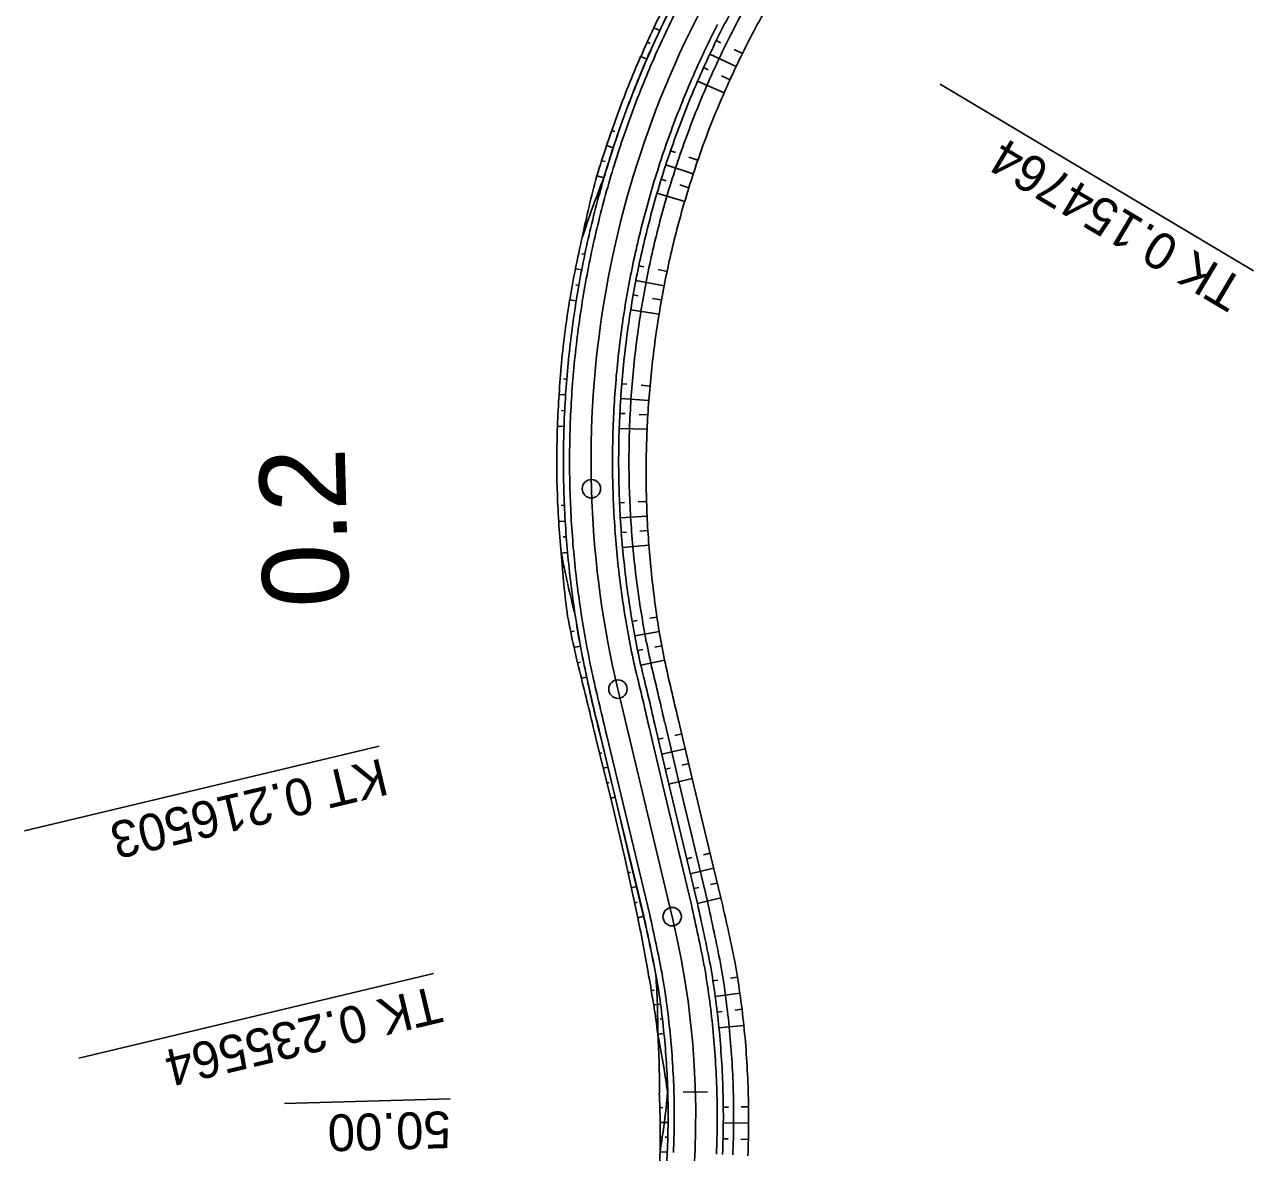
# Model space of a CAD drawing. Extents: x -481645 to -478728, y -1113199 to -1110710.
# Drawn here: x -479577.1 to -479477, y -1112599.2 to -1112507.3 of the extents above; entities that cross this region are included whole.
import ezdxf

# ---------------------------------------------------------------- set-up
doc = ezdxf.new("R2010")
doc.units = 0
for name, color, linetype in [('CP14_HRANA_TELESO', 7, 'Continuous'), ('CP14_OSA', 7, 'Continuous'), ('CP14_PRIKOP', 7, 'Continuous'), ('CP1_HATCH_SLOPE_L', 7, 'Continuous'), ('CP1_HATCH_SLOPE_R', 7, 'Continuous'), ('CP1_HLBODY', 7, 'Continuous'), ('CP1_HRANA_TELESO', 7, 'Continuous'), ('CP1_OSA', 7, 'Continuous'), ('CP1_STANICENI', 7, 'Continuous'), ('CP1_VOZOVKA', 7, 'Continuous'), ('CP1_ZPEVKRAJ', 7, 'Continuous')]:
    doc.layers.add(name, color=color, linetype=linetype)

msp = doc.modelspace()

# ---------------------------------------------------------------- linework, layer by layer
at = {"layer": 'CP14_HRANA_TELESO'}
for p, q in [((-479520.79, -1112508.65), (-479520.41, -1112508.84)), ((-479521.31, -1112509.75), (-479519.17, -1112510.76)), ((-479519.34, -1112509.36), (-479518.66, -1112509.7)), ((-479521.82, -1112510.85), (-479521.44, -1112511.02)), ((-479522.31, -1112511.96), (-479520.14, -1112512.9)), ((-479520.36, -1112511.51), (-479519.66, -1112511.83)), ((-479524.51, -1112517.62), (-479524.12, -1112517.76)), ((-479524.9, -1112518.77), (-479522.67, -1112519.5)), ((-479523.01, -1112518.14), (-479522.29, -1112518.39)), ((-479525.27, -1112519.93), (-479524.87, -1112520.06)), ((-479523.75, -1112520.4), (-479523.03, -1112520.63)), ((-479525.62, -1112521.09), (-479523.36, -1112521.75)), ((-479527.09, -1112526.99), (-479526.68, -1112527.07)), ((-479525.53, -1112527.31), (-479524.8, -1112527.47)), ((-479527.33, -1112528.18), (-479525.03, -1112528.62)), ((-479527.55, -1112529.37), (-479527.14, -1112529.45)), ((-479525.99, -1112529.65), (-479525.24, -1112529.78)), ((-479527.75, -1112530.57), (-479525.44, -1112530.94)), ((-479528.48, -1112536.6), (-479528.07, -1112536.63)), ((-479526.91, -1112536.73), (-479526.18, -1112536.79)), ((-479528.57, -1112537.81), (-479526.28, -1112537.96)), ((-479528.64, -1112539.02), (-479528.22, -1112539.04)), ((-479527.08, -1112539.1), (-479526.36, -1112539.14)), ((-479528.69, -1112540.24), (-479526.42, -1112540.31)), ((-479528.67, -1112546.31), (-479528.25, -1112546.29)), ((-479527.15, -1112546.24), (-479526.46, -1112546.21)), ((-479528.6, -1112547.52), (-479526.42, -1112547.39)), ((-479528.52, -1112548.73), (-479528.1, -1112548.7)), ((-479527.02, -1112548.62), (-479526.36, -1112548.57)), ((-479528.42, -1112549.95), (-479526.28, -1112549.75)), ((-479527.64, -1112555.97), (-479527.22, -1112555.9)), ((-479526.21, -1112555.72), (-479525.61, -1112555.62)), ((-479527.42, -1112557.16), (-479525.42, -1112556.79)), ((-479525.79, -1112558.07), (-479525.22, -1112557.96)), ((-479527.19, -1112558.35), (-479526.78, -1112558.27)), ((-479526.94, -1112559.54), (-479524.99, -1112559.12)), ((-479525.51, -1112565.58), (-479525.11, -1112565.49)), ((-479524.15, -1112565.26), (-479523.6, -1112565.13)), ((-479525.22, -1112566.8), (-479523.32, -1112566.35)), ((-479524.93, -1112568.02), (-479524.53, -1112567.92)), ((-479523.57, -1112567.69), (-479523.03, -1112567.56)), ((-479524.64, -1112569.23), (-479522.74, -1112568.78)), ((-479521.84, -1112574.99), (-479521.3, -1112574.86)), ((-479523.19, -1112575.31), (-479522.78, -1112575.21)), ((-479522.9, -1112576.53), (-479521, -1112576.07)), ((-479522.61, -1112577.74), (-479522.2, -1112577.65)), ((-479521.25, -1112577.42), (-479520.7, -1112577.29)), ((-479522.32, -1112578.96), (-479520.41, -1112578.5)), ((-479519.64, -1112585.05), (-479519.06, -1112584.96)), ((-479521.06, -1112585.27), (-479520.65, -1112585.2)), ((-479520.87, -1112586.54), (-479518.86, -1112586.27)), ((-479520.71, -1112587.82), (-479520.3, -1112587.77)), ((-479519.28, -1112587.65), (-479518.69, -1112587.58)), ((-479520.57, -1112589.1), (-479518.54, -1112588.9)), ((-479520.22, -1112595.54), (-479519.8, -1112595.54)), ((-479518.77, -1112595.53), (-479518.16, -1112595.52)), ((-479520.22, -1112596.83), (-479518.15, -1112596.85)), ((-479520.24, -1112598.12), (-479519.82, -1112598.13)), ((-479518.78, -1112598.16), (-479518.16, -1112598.18))]:
    msp.add_line(p, q, dxfattribs=at)
at = {"layer": 'CP14_OSA'}
msp.add_circle((-479530.96, -1112545.16), 0.75, dxfattribs=at)
at = {"layer": 'CP14_PRIKOP'}
for p, q in [((-479525.38, -1112507.83), (-479525.87, -1112507.6)), ((-479526.17, -1112508.88), (-479526.42, -1112508.77)), ((-479525.92, -1112509), (-479525.93, -1112508.99)), ((-479526.44, -1112510.17), (-479526.94, -1112509.95)), ((-479529.04, -1112516.06), (-479529.3, -1112515.98)), ((-479528.77, -1112516.16), (-479528.77, -1112516.16)), ((-479529.18, -1112517.38), (-479529.72, -1112517.2)), ((-479529.85, -1112518.51), (-479530.13, -1112518.43)), ((-479529.57, -1112518.6), (-479529.57, -1112518.6)), ((-479529.93, -1112519.83), (-479530.51, -1112519.66)), ((-479531.99, -1112525.96), (-479531.99, -1112525.96)), ((-479531.5, -1112526.06), (-479531.74, -1112526.01)), ((-479531.75, -1112527.32), (-479532.26, -1112527.23)), ((-479532.5, -1112528.5), (-479532.5, -1112528.5)), ((-479531.98, -1112528.59), (-479532.24, -1112528.54)), ((-479532.2, -1112529.85), (-479532.73, -1112529.77)), ((-479533.5, -1112536.19), (-479533.5, -1112536.19)), ((-479532.97, -1112536.23), (-479533.23, -1112536.21)), ((-479533.06, -1112537.51), (-479533.6, -1112537.48)), ((-479533.67, -1112538.77), (-479533.67, -1112538.77)), ((-479533.14, -1112538.8), (-479533.4, -1112538.78)), ((-479533.19, -1112540.08), (-479533.72, -1112540.06)), ((-479533.7, -1112546.53), (-479533.7, -1112546.53)), ((-479533.16, -1112546.51), (-479533.43, -1112546.52)), ((-479533.1, -1112547.79), (-479533.62, -1112547.82)), ((-479533.53, -1112549.11), (-479533.53, -1112549.11)), ((-479533.01, -1112549.07), (-479533.27, -1112549.09)), ((-479532.9, -1112550.35), (-479533.42, -1112550.4)), ((-479532.36, -1112556.77), (-479532.65, -1112556.82)), ((-479532.07, -1112556.72), (-479532.08, -1112556.72)), ((-479531.85, -1112557.99), (-479532.38, -1112558.09)), ((-479531.85, -1112559.3), (-479532.09, -1112559.35)), ((-479531.6, -1112559.25), (-479531.61, -1112559.25)), ((-479531.34, -1112560.51), (-479531.78, -1112560.6)), ((-479530.1, -1112566.68), (-479530.29, -1112566.73)), ((-479529.89, -1112566.63), (-479529.9, -1112566.63)), ((-479529.6, -1112567.85), (-479529.99, -1112567.94)), ((-479529.31, -1112569.06), (-479529.31, -1112569.06)), ((-479529.51, -1112569.11), (-479529.69, -1112569.15)), ((-479529.02, -1112570.28), (-479529.39, -1112570.37)), ((-479527.78, -1112576.41), (-479527.97, -1112576.45)), ((-479527.57, -1112576.36), (-479527.57, -1112576.36)), ((-479527.28, -1112577.57), (-479527.71, -1112577.67)), ((-479527.22, -1112578.84), (-479527.43, -1112578.9)), ((-479526.99, -1112578.79), (-479526.99, -1112578.79)), ((-479526.7, -1112580), (-479527.17, -1112580.12)), ((-479525.85, -1112586.01), (-479526.07, -1112586.04)), ((-479525.51, -1112585.95), (-479525.57, -1112585.96)), ((-479525.33, -1112587.15), (-479525.88, -1112587.22)), ((-479525.63, -1112588.4), (-479525.7, -1112588.41)), ((-479525.18, -1112588.35), (-479525.37, -1112588.37)), ((-479525.05, -1112589.55), (-479525.55, -1112589.6)), ((-479525.13, -1112595.59), (-479525.38, -1112595.6)), ((-479524.72, -1112595.59), (-479524.79, -1112595.59)), ((-479524.72, -1112596.8), (-479525.35, -1112596.79)), ((-479525.26, -1112598), (-479525.35, -1112597.99)), ((-479524.74, -1112598.01), (-479524.96, -1112598)), ((-479524.78, -1112599.22), (-479525.36, -1112599.19))]:
    msp.add_line(p, q, dxfattribs=at)
at = {"layer": 'CP1_HATCH_SLOPE_L'}
for p, q in [((-479542.48, -1112594.88), (-479555.98, -1112595.26)), ((-479523.49, -1112594.34), (-479521.49, -1112594.29))]:
    msp.add_line(p, q, dxfattribs=at)
at = {"layer": 'CP1_HATCH_SLOPE_R'}
for p, q in [((-479477.02, -1112527.4), (-479502.53, -1112512.2)), ((-479548.26, -1112566.14), (-479577.15, -1112573.03)), ((-479543.83, -1112584.67), (-479572.72, -1112591.57))]:
    msp.add_line(p, q, dxfattribs=at)
for centre in [(-479528.8, -1112561.49), (-479524.38, -1112580.03)]:
    msp.add_circle(centre, 0.75, dxfattribs=at)
at = {"layer": 'CP1_HLBODY'}
for p, q in [((-479526.29, -1112564.49), (-479525.13, -1112569.35)), ((-479529.69, -1112565.3), (-479528.53, -1112570.16)), ((-479525.13, -1112569.35), (-479523.97, -1112574.21)), ((-479528.53, -1112570.16), (-479527.37, -1112575.02)), ((-479527.37, -1112575.02), (-479526.21, -1112579.89)), ((-479523.97, -1112574.21), (-479522.81, -1112579.07))]:
    msp.add_line(p, q, dxfattribs=at)
for centre, radius, start, end in [((-479450.99, -1112542.91), 81.75, 152.9594, 156.5404), ((-479450.99, -1112542.91), 78.25, 152.9594, 156.5404), ((-479450.99, -1112542.91), 81.75, 156.5404, 160.1214), ((-479450.99, -1112542.91), 78.25, 156.5404, 160.1214), ((-479450.99, -1112542.91), 81.75, 160.1214, 163.7024), ((-479450.99, -1112542.91), 78.25, 160.1214, 163.7024), ((-479450.99, -1112542.91), 81.75, 163.7024, 167.2834), ((-479450.99, -1112542.91), 78.25, 163.7024, 167.2834), ((-479450.99, -1112542.91), 81.75, 167.2834, 170.8644), ((-479450.99, -1112542.91), 78.25, 167.2834, 170.8644), ((-479450.99, -1112542.91), 81.75, 170.8644, 174.4454), ((-479450.99, -1112542.91), 78.25, 170.8644, 174.4453), ((-479450.99, -1112542.91), 81.75, 174.4454, 178.0263), ((-479450.99, -1112542.91), 78.25, 174.4453, 178.0263), ((-479450.99, -1112542.91), 81.75, 178.0263, 181.6073), ((-479450.99, -1112542.91), 78.25, 178.0263, 181.6073), ((-479450.99, -1112542.91), 81.75, 181.6073, 185.1883), ((-479450.99, -1112542.91), 78.25, 181.6073, 185.1883), ((-479450.99, -1112542.91), 78.25, 185.1883, 188.7693), ((-479450.99, -1112542.91), 81.75, 185.1883, 188.7693), ((-479450.99, -1112542.91), 78.25, 188.7693, 192.3503), ((-479450.99, -1112542.91), 81.75, 188.7693, 192.3503), ((-479646.41, -1112590.26), 122.85, 12.1092, 14.4259), ((-479055.23, -1112450.88), 488.07, 192.9672, 193.558), ((-479732.96, -1112625.63), 215.25, 11.1319, 12.4921), ((-479726.1, -1112624.22), 204.75, 11.1371, 12.505), ((-479592.46, -1112596.28), 71.75, 5.7036, 9.7962), ((-479592.46, -1112596.28), 68.25, 5.7036, 9.7962), ((-479592.46, -1112596.28), 68.25, 1.6111, 5.7036), ((-479592.46, -1112596.28), 71.75, 1.6111, 5.7036), ((-479592.46, -1112596.28), 68.25, 357.5185, 1.6111), ((-479592.46, -1112596.28), 71.75, 357.5185, 1.6111)]:
    msp.add_arc(centre, radius, start, end, dxfattribs=at)
at = {"layer": 'CP1_HRANA_TELESO'}
for p, q in [((-479523.89, -1112563.91), (-479522.74, -1112568.78)), ((-479530.59, -1112565.51), (-479529.39, -1112570.37)), ((-479522.74, -1112568.78), (-479521.59, -1112573.65)), ((-479529.39, -1112570.37), (-479528.24, -1112575.23)), ((-479521.59, -1112573.65), (-479520.41, -1112578.5)), ((-479528.24, -1112575.23), (-479527.17, -1112580.12))]:
    msp.add_line(p, q, dxfattribs=at)
for centre, radius, start, end in [((-479451.06, -1112543.04), 75.37, 149.269, 152.85), ((-479451, -1112542.94), 82.79, 152.9406, 156.5215), ((-479451.05, -1112543.04), 75.38, 152.8503, 156.4313), ((-479451.05, -1112543.05), 82.8, 156.4382, 160.0191), ((-479451.1, -1112543.18), 75.39, 156.3246, 159.9056), ((-479451.21, -1112543.59), 82.83, 159.6276, 163.2087), ((-479451, -1112542.95), 75.4, 160.0963, 163.6772), ((-479450.6, -1112541.33), 82.8, 164.8303, 168.412), ((-479451, -1112542.93), 75.4, 163.6863, 167.2673), ((-479451.11, -1112543.53), 82.77, 166.8457, 170.4268), ((-479450.99, -1112542.93), 75.41, 167.2705, 170.8515), ((-479450.99, -1112542.88), 82.79, 170.8858, 174.4668), ((-479451.04, -1112543.28), 75.42, 170.5824, 174.1635), ((-479450.99, -1112542.88), 82.78, 174.4657, 178.0466), ((-479451.04, -1112543.58), 75.45, 173.9416, 177.5227), ((-479450.99, -1112543.05), 82.79, 177.9315, 181.5125), ((-479451, -1112543.85), 75.5, 177.318, 180.8993), ((-479450.94, -1112543.96), 75.56, 180.8167, 184.398), ((-479451.01, -1112542.57), 82.78, 181.8447, 185.4257), ((-479450.85, -1112544.18), 75.63, 184.2203, 187.8018), ((-479450.81, -1112544.56), 82.82, 184.0404, 187.6221), ((-479450.76, -1112544.23), 75.72, 187.757, 191.3386), ((-479451.54, -1112540.21), 82.79, 190.676, 194.259), ((-479340.15, -1112518.87), 189.18, 192.2848, 193.775), ((-479756.62, -1112617.43), 231.91, 12.9353, 14.1831), ((-479737.47, -1112628.79), 222.81, 11.689, 13.0438), ((-479724.82, -1112619.13), 201.46, 9.7949, 11.1667), ((-479592.42, -1112596.59), 74.28, 5.9416, 10.0341), ((-479592.28, -1112597.58), 67.2, 6.8166, 10.9099), ((-479592.45, -1112596.51), 74.3, 1.7819, 5.8745), ((-479592.58, -1112593.71), 67.16, 359.4118, 3.5074), ((-479592.46, -1112597.7), 67.11, 358.7224, 2.8158), ((-479592.47, -1112596.58), 74.32, 357.7424, 1.835), ((-479592.43, -1112595.83), 67.15, 353.0407, 357.1334)]:
    msp.add_arc(centre, radius, start, end, dxfattribs=at)
at = {"layer": 'CP1_OSA'}
msp.add_line((-479528.8, -1112561.49), (-479524.38, -1112580.03), dxfattribs=at)
for centre, radius, start, end in [((-479450.99, -1112542.91), 80, 149.2096, 193.4269), ((-479592.46, -1112596.28), 70, 327.8575, 13.4269)]:
    msp.add_arc(centre, radius, start, end, dxfattribs=at)
at = {"layer": 'CP1_STANICENI'}
for p, q in [((-479526.29, -1112564.49), (-479525.13, -1112569.35)), ((-479529.69, -1112565.3), (-479528.53, -1112570.16)), ((-479525.13, -1112569.35), (-479523.97, -1112574.21)), ((-479528.53, -1112570.16), (-479527.37, -1112575.02)), ((-479527.37, -1112575.02), (-479526.21, -1112579.89)), ((-479523.97, -1112574.21), (-479522.81, -1112579.07))]:
    msp.add_line(p, q, dxfattribs=at)
for centre, radius, start, end in [((-479450.99, -1112542.91), 81.75, 152.9594, 156.5404), ((-479450.99, -1112542.91), 78.25, 152.9594, 156.5404), ((-479450.99, -1112542.91), 81.75, 156.5404, 160.1214), ((-479450.99, -1112542.91), 78.25, 156.5404, 160.1214), ((-479450.99, -1112542.91), 81.75, 160.1214, 163.7024), ((-479450.99, -1112542.91), 78.25, 160.1214, 163.7024), ((-479450.99, -1112542.91), 81.75, 163.7024, 167.2834), ((-479450.99, -1112542.91), 78.25, 163.7024, 167.2834), ((-479450.99, -1112542.91), 81.75, 167.2834, 170.8644), ((-479450.99, -1112542.91), 78.25, 167.2834, 170.8644), ((-479450.99, -1112542.91), 81.75, 170.8644, 174.4454), ((-479450.99, -1112542.91), 78.25, 170.8644, 174.4453), ((-479450.99, -1112542.91), 81.75, 174.4454, 178.0263), ((-479450.99, -1112542.91), 78.25, 174.4453, 178.0263), ((-479450.99, -1112542.91), 81.75, 178.0263, 181.6073), ((-479450.99, -1112542.91), 78.25, 178.0263, 181.6073), ((-479450.99, -1112542.91), 81.75, 181.6073, 185.1883), ((-479450.99, -1112542.91), 78.25, 181.6073, 185.1883), ((-479450.99, -1112542.91), 78.25, 185.1883, 188.7693), ((-479450.99, -1112542.91), 81.75, 185.1883, 188.7693), ((-479450.99, -1112542.91), 78.25, 188.7693, 192.3503), ((-479450.99, -1112542.91), 81.75, 188.7693, 192.3503), ((-479646.41, -1112590.26), 122.85, 12.1092, 14.4259), ((-479055.23, -1112450.88), 488.07, 192.9672, 193.558), ((-479732.96, -1112625.63), 215.25, 11.1319, 12.4921), ((-479726.1, -1112624.22), 204.75, 11.1371, 12.505), ((-479592.46, -1112596.28), 71.75, 5.7036, 9.7962), ((-479592.46, -1112596.28), 68.25, 5.7036, 9.7962), ((-479592.46, -1112596.28), 68.25, 1.6111, 5.7036), ((-479592.46, -1112596.28), 71.75, 1.6111, 5.7036), ((-479592.46, -1112596.28), 68.25, 357.5185, 1.6111), ((-479592.46, -1112596.28), 71.75, 357.5185, 1.6111)]:
    msp.add_arc(centre, radius, start, end, dxfattribs=at)
at = {"layer": 'CP1_VOZOVKA'}
for p, q in [((-479525.8, -1112564.37), (-479524.64, -1112569.23)), ((-479530.18, -1112565.41), (-479529.02, -1112570.28)), ((-479524.64, -1112569.23), (-479523.48, -1112574.1)), ((-479529.02, -1112570.28), (-479527.86, -1112575.14)), ((-479523.48, -1112574.1), (-479522.32, -1112578.96)), ((-479527.86, -1112575.14), (-479526.7, -1112580))]:
    msp.add_line(p, q, dxfattribs=at)
for centre, radius, start, end in [((-479450.99, -1112542.91), 77.75, 149.3784, 152.9594), ((-479450.99, -1112542.91), 82.25, 152.9594, 156.5404), ((-479450.99, -1112542.91), 77.75, 152.9594, 156.5404), ((-479450.99, -1112542.91), 82.25, 156.5404, 160.1214), ((-479450.99, -1112542.91), 77.75, 156.5404, 160.1214), ((-479450.99, -1112542.91), 82.25, 160.1214, 163.7024), ((-479450.99, -1112542.91), 77.75, 160.1214, 163.7024), ((-479450.99, -1112542.91), 82.25, 163.7024, 167.2834), ((-479450.99, -1112542.91), 77.75, 163.7024, 167.2834), ((-479450.99, -1112542.91), 82.25, 167.2834, 170.8644), ((-479450.99, -1112542.91), 77.75, 167.2834, 170.8644), ((-479450.99, -1112542.91), 82.25, 170.8644, 174.4454), ((-479450.99, -1112542.91), 77.75, 170.8644, 174.4453), ((-479450.99, -1112542.91), 82.25, 174.4454, 178.0263), ((-479450.99, -1112542.91), 77.75, 174.4453, 178.0263), ((-479450.99, -1112542.91), 82.25, 178.0263, 181.6073), ((-479450.99, -1112542.91), 77.75, 178.0263, 181.6073), ((-479450.99, -1112542.91), 82.25, 181.6073, 185.1883), ((-479450.99, -1112542.91), 77.75, 181.6073, 185.1883), ((-479450.99, -1112542.91), 77.75, 185.1883, 188.7693), ((-479450.99, -1112542.91), 82.25, 185.1883, 188.7693), ((-479450.99, -1112542.91), 77.75, 188.7693, 192.3503), ((-479450.99, -1112542.91), 82.25, 188.7693, 192.3503), ((-479695.67, -1112601.88), 173.96, 12.4518, 14.0848), ((-479444.64, -1112542.66), 88.52, 191.6298, 194.894), ((-479733.94, -1112625.84), 216.75, 11.1312, 12.4903), ((-479725.12, -1112624.02), 203.25, 11.1379, 12.507), ((-479592.46, -1112596.28), 72.25, 5.7036, 9.7962), ((-479592.46, -1112596.28), 67.75, 5.7036, 9.7962), ((-479592.46, -1112596.28), 67.75, 1.6111, 5.7036), ((-479592.46, -1112596.28), 72.25, 1.6111, 5.7036), ((-479592.46, -1112596.28), 67.75, 357.5185, 1.6111), ((-479592.46, -1112596.28), 72.25, 357.5185, 1.6111), ((-479592.46, -1112596.28), 67.75, 353.426, 357.5185)]:
    msp.add_arc(centre, radius, start, end, dxfattribs=at)
at = {"layer": 'CP1_ZPEVKRAJ'}
for p, q in [((-479524.99, -1112564.18), (-479523.83, -1112569.04)), ((-479530.19, -1112565.42), (-479529.03, -1112570.28)), ((-479523.83, -1112569.04), (-479522.67, -1112573.9)), ((-479529.03, -1112570.28), (-479527.87, -1112575.14)), ((-479522.67, -1112573.9), (-479521.51, -1112578.77)), ((-479527.87, -1112575.14), (-479526.71, -1112580.01))]:
    msp.add_line(p, q, dxfattribs=at)
for centre, radius, start, end in [((-479450.99, -1112542.91), 76.91, 149.3784, 152.9594), ((-479450.99, -1112542.91), 82.26, 152.9594, 156.5404), ((-479450.99, -1112542.91), 76.91, 152.9594, 156.5404), ((-479450.99, -1112542.91), 82.26, 156.5404, 160.1214), ((-479450.99, -1112542.91), 76.91, 156.5404, 160.1214), ((-479450.99, -1112542.91), 82.26, 160.1214, 163.7024), ((-479450.99, -1112542.91), 76.91, 160.1214, 163.7024), ((-479453.29, -1112550.33), 82.5, 158.3023, 161.8992), ((-479450.99, -1112542.91), 76.91, 163.7024, 167.2834), ((-479450.99, -1112542.91), 76.91, 167.2834, 170.8644), ((-479450.99, -1112542.91), 76.91, 170.8644, 174.4453), ((-479450.99, -1112542.91), 76.91, 174.4453, 178.0263), ((-479450.99, -1112542.91), 76.91, 178.0263, 181.6073), ((-479450.99, -1112542.91), 76.91, 181.6073, 185.1883), ((-479450.99, -1112542.91), 76.91, 185.1883, 188.7693), ((-479452.37, -1112534.91), 82.51, 190.8226, 194.4211), ((-479450.99, -1112542.91), 76.91, 188.7693, 192.3503), ((-479450.99, -1112542.91), 82.26, 188.7693, 192.3503), ((-479887.22, -1112647.06), 371.59, 12.8885, 13.6505), ((-479411.39, -1112534.83), 122.67, 192.0843, 194.4395), ((-479735.58, -1112626.17), 219.26, 11.13, 12.4874), ((-479725.1, -1112624.02), 203.22, 11.1379, 12.507), ((-479592.46, -1112596.28), 73.09, 5.7036, 9.7962), ((-479593.04, -1112589.45), 67.49, 359.871, 3.9848), ((-479592.46, -1112596.28), 73.09, 1.6111, 5.7036), ((-479591.68, -1112603.1), 67.49, 7.4225, 11.5363), ((-479591.93, -1112588.29), 67.45, 350.6997, 354.8213), ((-479592.46, -1112596.28), 73.09, 357.5185, 1.6111)]:
    msp.add_arc(centre, radius, start, end, dxfattribs=at)

# ---------------------------------------------------------------- texts
at = {"layer": 'CP14_OSA'}
msp.add_text('0.2', height=7, rotation=91.5617, dxfattribs=at).set_placement((-479550.71, -1112554.76))
at = {"layer": 'CP1_HATCH_SLOPE_L'}
msp.add_text('50.00', height=2.999, rotation=181.6111, dxfattribs=at).set_placement((-479542.46, -1112595.88))
at = {"layer": 'CP1_HATCH_SLOPE_R'}
for s, height, rotation, p in [('TK 0.154764', 3, 149.2096, (-479477.53, -1112528.26)), ('KT 0.216503', 2.999, 193.4269, (-479548.02, -1112567.11)), ('TK 0.235564', 2.999, 193.4269, (-479543.6, -1112585.65))]:
    msp.add_text(s, height=height, rotation=rotation, dxfattribs=at).set_placement(p)

doc.saveas('drawing.dxf')
